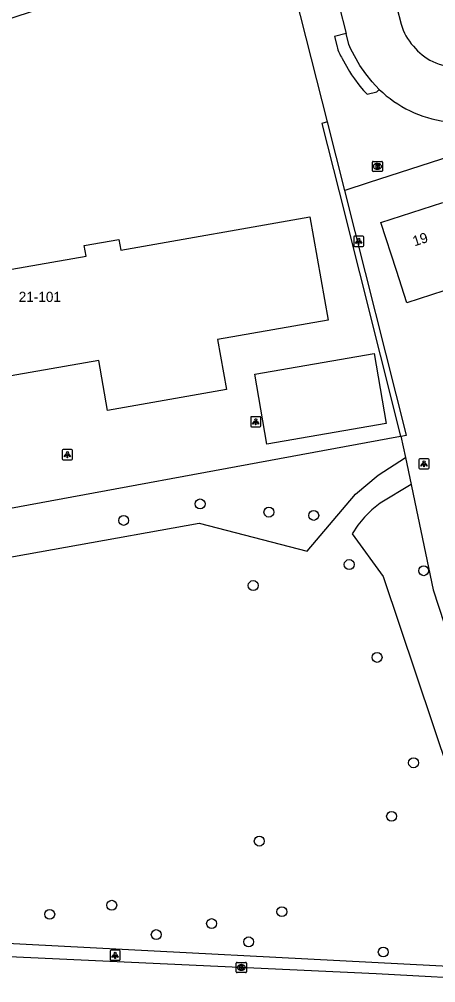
# Model space of a CAD drawing. Extents: x 161253 to 161848, y 384872 to 385383.
# Drawn here: x 161391.4 to 161432.4, y 384951.8 to 385046.9 of the extents above; entities that cross this region are included whole.
import ezdxf

# ---------------------------------------------------------------- set-up
doc = ezdxf.new("R2010")
doc.units = 0
for name, color, linetype in [('IMGEO_Boom', 7, 'Continuous'), ('IMGEO_Brandkraan', 7, 'Continuous'), ('IMGEO_Groenvoorziening', 7, 'Continuous'), ('IMGEO_Haag', 7, 'Continuous'), ('IMGEO_Kolk', 7, 'Continuous'), ('IMGEO_Lichtpunt', 7, 'Continuous'), ('IMGEO_Pand', 7, 'Continuous'), ('IMGEO_Pand_nummerreeks', 7, 'Continuous'), ('IMGEO_Pand_vergunning_verleend', 7, 'Continuous'), ('IMGEO_Rijbaan_lokaal_open', 7, 'Continuous'), ('IMGEO_Voetpad_open', 7, 'Continuous')]:
    doc.layers.add(name, color=color, linetype=linetype)

msp = doc.modelspace()

# ---------------------------------------------------------------- linework, layer by layer
at = {"layer": 'IMGEO_Boom'}
for centre in [(161409.193, 384999.044), (161415.979, 384998.236), (161401.652, 384997.416), (161420.399, 384997.91), (161423.899, 384993.064), (161431.249, 384992.453), (161414.431, 384990.989), (161426.651, 384983.899), (161430.243, 384973.495), (161428.081, 384968.214), (161415.029, 384965.761), (161400.476, 384959.436), (161394.357, 384958.539), (161417.258, 384958.8), (161410.326, 384957.625), (161404.866, 384956.537), (161413.98, 384955.819), (161427.258, 384954.817)]:
    msp.add_circle(centre, 0.489, dxfattribs=at)
at = {"layer": 'IMGEO_Brandkraan'}
for p, q in [((161426.183, 385031.932), (161426.183, 385032.784)), ((161426.258, 385032.858), (161427.11, 385032.858)), ((161426.694, 385032.078), (161426.669, 385032.078)), ((161426.671, 385032.638), (161426.696, 385032.638)), ((161427.184, 385032.784), (161427.184, 385031.932)), ((161427.11, 385031.858), (161426.258, 385031.858))]:
    msp.add_line(p, q, dxfattribs=at)
for points in [[(161426.183, 385031.932), (161426.183, 385032.784)], [(161426.258, 385032.858), (161427.11, 385032.858)], [(161426.531, 385032.558), (161426.531, 385032.158), (161426.744, 385032.158)], [(161426.762, 385032.558), (161426.531, 385032.558)], [(161426.71, 385032.477), (161426.656, 385032.477), (161426.656, 385032.401)], [(161426.656, 385032.401), (161426.709, 385032.401)], [(161426.718, 385032.325), (161426.656, 385032.325), (161426.656, 385032.244)], [(161426.656, 385032.244), (161426.718, 385032.244)], [(161427.184, 385032.784), (161427.184, 385031.932)], [(161427.11, 385031.858), (161426.258, 385031.858)]]:
    msp.add_lwpolyline(points, dxfattribs=at)
for centre, radius, start, end in [((161426.26, 385032.782), 0.0765, 91.55205, 178.44795), ((161426.26, 385032.782), 0.0765, 91.55205, 178.44795), ((161426.711, 385032.439), 0.0379, 267.82845, 90.93552), ((161426.719, 385032.284), 0.0404, 269.87594, 90.50774), ((161426.75, 385032.409), 0.251, 268.66757, 293.53466), ((161426.766, 385032.413), 0.145, 59.4692, 91.53667), ((161426.791, 385032.46), 0.0922, 285.51372, 58.15012), ((161426.796, 385032.268), 0.105, 301.31148, 78.98903), ((161427.108, 385032.782), 0.0765, 1.55205, 88.44795), ((161427.108, 385032.782), 0.0765, 1.55205, 88.44795), ((161426.26, 385031.934), 0.0765, 181.55205, 268.44795), ((161426.26, 385031.934), 0.0765, 181.55205, 268.44795), ((161427.108, 385031.934), 0.0765, 271.55205, 358.44795), ((161427.108, 385031.934), 0.0765, 271.55205, 358.44795)]:
    msp.add_arc(centre, radius, start, end, dxfattribs=at)
for centre, major_axis, ratio, start_param, end_param in [((161426.67, 385032.358), (-0.387, 0.002), 0.722429, 4.712389, 7.853982), ((161426.695, 385032.358), (-0.39, 0.002), 0.717154, 1.570796, 4.712389)]:
    msp.add_ellipse(centre, major_axis=major_axis, ratio=ratio, start_param=start_param, end_param=end_param, dxfattribs=at)
at = {"layer": 'IMGEO_Groenvoorziening'}
for points in [[(161381.538, 384996.968), (161428.963, 385005.723)], [(161429.001, 385005.73), (161429.448, 385003.612)], [(161385.699, 384955.916), (161382.254, 384992.314), (161382.704, 384992.395), (161409.099, 384997.144), (161419.747, 384994.367), (161424.534, 385000), (161426.767, 385001.869), (161429.448, 385003.612)], [(161429.448, 385003.612), (161430.009, 385000.952)], [(161430.009, 385000.952), (161426.954, 384999.107), (161426.145, 384998.467), (161425.408, 384997.745), (161424.75, 384996.95), (161424.179, 384996.091), (161427.248, 384991.885), (161440.288, 384952.96)], [(161430.009, 385000.952), (161430.209, 385000), (161432.194, 384990.572), (161444.094, 384954.097), (161443.567, 384951.787)]]:
    msp.add_lwpolyline(points, dxfattribs=at)
at = {"layer": 'IMGEO_Haag'}
for points in [[(161421.765, 385036.754), (161421.184, 385036.607), (161422.894, 385029.848), (161428.963, 385005.723)], [(161429.001, 385005.73), (161429.554, 385005.833), (161423.476, 385029.994)], [(161428.963, 385005.723), (161429.001, 385005.73)]]:
    msp.add_lwpolyline(points, dxfattribs=at)
at = {"layer": 'IMGEO_Kolk'}
for p, q in [((161412.759, 384952.865), (161412.759, 384953.717)), ((161412.834, 384953.791), (161413.686, 384953.791)), ((161413.247, 384953.571), (161413.272, 384953.571)), ((161413.76, 384953.717), (161413.76, 384952.865)), ((161413.686, 384952.791), (161412.834, 384952.791)), ((161413.27, 384953.011), (161413.245, 384953.011))]:
    msp.add_line(p, q, dxfattribs=at)
for points in [[(161412.759, 384952.865), (161412.759, 384953.717)], [(161412.834, 384953.791), (161413.686, 384953.791)], [(161413.08, 384953.491), (161413.203, 384953.491), (161413.203, 384953.34), (161413.333, 384953.491), (161413.497, 384953.491), (161413.351, 384953.34), (161413.504, 384953.091), (161413.352, 384953.091), (161413.267, 384953.255), (161413.203, 384953.188), (161413.203, 384953.091), (161413.08, 384953.091), (161413.08, 384953.491)], [(161413.76, 384953.717), (161413.76, 384952.865)], [(161413.686, 384952.791), (161412.834, 384952.791)]]:
    msp.add_lwpolyline(points, dxfattribs=at)
for centre, start, end in [((161412.836, 384953.715), 91.55205, 178.44795), ((161412.836, 384953.715), 91.55205, 178.44795), ((161413.684, 384953.715), 1.55205, 88.44795), ((161413.684, 384953.715), 1.55205, 88.44795), ((161412.836, 384952.867), 181.55205, 268.44795), ((161412.836, 384952.867), 181.55205, 268.44795), ((161413.684, 384952.867), 271.55205, 358.44795), ((161413.684, 384952.867), 271.55205, 358.44795)]:
    msp.add_arc(centre, 0.0765, start, end, dxfattribs=at)
for centre, major_axis, ratio, start_param, end_param in [((161413.246, 384953.291), (-0.387, 0.002), 0.722429, 4.712389, 7.853982), ((161413.271, 384953.291), (-0.39, 0.002), 0.717154, 1.570796, 4.712389)]:
    msp.add_ellipse(centre, major_axis=major_axis, ratio=ratio, start_param=start_param, end_param=end_param, dxfattribs=at)
at = {"layer": 'IMGEO_Lichtpunt'}
for p, q in [((161424.342, 385025.37), (161424.342, 385024.563)), ((161424.342, 385025.37), (161424.342, 385024.563)), ((161425.244, 385025.465), (161424.436, 385025.465)), ((161425.244, 385025.465), (161424.436, 385025.465)), ((161425.338, 385024.563), (161425.338, 385025.37)), ((161425.338, 385024.563), (161425.338, 385025.37)), ((161424.436, 385024.469), (161425.244, 385024.469)), ((161424.436, 385024.469), (161425.244, 385024.469)), ((161414.182, 385007.559), (161414.182, 385006.752)), ((161414.182, 385007.559), (161414.182, 385006.752)), ((161415.084, 385007.654), (161414.276, 385007.654)), ((161415.084, 385007.654), (161414.276, 385007.654)), ((161415.178, 385006.752), (161415.178, 385007.559)), ((161415.178, 385006.752), (161415.178, 385007.559)), ((161414.276, 385006.658), (161415.084, 385006.658)), ((161414.276, 385006.658), (161415.084, 385006.658)), ((161396.504, 385004.406), (161395.696, 385004.406)), ((161396.504, 385004.406), (161395.696, 385004.406)), ((161395.602, 385004.311), (161395.602, 385003.504)), ((161395.602, 385004.311), (161395.602, 385003.504)), ((161396.598, 385003.504), (161396.598, 385004.311)), ((161396.598, 385003.504), (161396.598, 385004.311)), ((161431.682, 385003.496), (161430.874, 385003.496)), ((161431.682, 385003.496), (161430.874, 385003.496)), ((161395.696, 385003.41), (161396.504, 385003.41)), ((161395.696, 385003.41), (161396.504, 385003.41)), ((161430.78, 385003.401), (161430.78, 385002.594)), ((161430.78, 385003.401), (161430.78, 385002.594)), ((161431.776, 385002.594), (161431.776, 385003.401)), ((161431.776, 385002.594), (161431.776, 385003.401)), ((161430.874, 385002.5), (161431.682, 385002.5)), ((161430.874, 385002.5), (161431.682, 385002.5)), ((161401.213, 384954.994), (161400.405, 384954.994)), ((161401.213, 384954.994), (161400.405, 384954.994)), ((161400.311, 384954.899), (161400.311, 384954.092)), ((161400.311, 384954.899), (161400.311, 384954.092)), ((161401.307, 384954.092), (161401.307, 384954.899)), ((161401.307, 384954.092), (161401.307, 384954.899)), ((161400.405, 384953.998), (161401.213, 384953.998)), ((161400.405, 384953.998), (161401.213, 384953.998))]:
    msp.add_line(p, q, dxfattribs=at)
for points in [[(161424.716, 385025.034), (161424.755, 385025.006), (161424.567, 385024.744), (161424.529, 385024.771), (161424.716, 385025.034)], [(161424.818, 385024.986), (161424.865, 385024.986), (161424.865, 385024.664), (161424.818, 385024.664), (161424.818, 385024.986)], [(161424.928, 385025.006), (161424.966, 385025.033), (161425.153, 385024.771), (161425.114, 385024.743), (161424.928, 385025.006)], [(161414.556, 385007.223), (161414.595, 385007.195), (161414.407, 385006.933), (161414.369, 385006.96), (161414.556, 385007.223)], [(161414.658, 385007.175), (161414.705, 385007.175), (161414.705, 385006.853), (161414.658, 385006.853), (161414.658, 385007.175)], [(161414.768, 385007.195), (161414.806, 385007.222), (161414.993, 385006.96), (161414.954, 385006.932), (161414.768, 385007.195)], [(161395.976, 385003.975), (161396.015, 385003.947), (161395.827, 385003.685), (161395.789, 385003.712), (161395.976, 385003.975)], [(161396.078, 385003.927), (161396.125, 385003.927), (161396.125, 385003.605), (161396.078, 385003.605), (161396.078, 385003.927)], [(161396.188, 385003.947), (161396.226, 385003.974), (161396.413, 385003.712), (161396.374, 385003.684), (161396.188, 385003.947)], [(161431.154, 385003.065), (161431.193, 385003.037), (161431.005, 385002.775), (161430.967, 385002.802), (161431.154, 385003.065)], [(161431.256, 385003.017), (161431.303, 385003.017), (161431.303, 385002.695), (161431.256, 385002.695), (161431.256, 385003.017)], [(161431.366, 385003.037), (161431.404, 385003.064), (161431.591, 385002.802), (161431.552, 385002.774), (161431.366, 385003.037)], [(161400.685, 384954.563), (161400.724, 384954.535), (161400.536, 384954.273), (161400.498, 384954.3), (161400.685, 384954.563)], [(161400.787, 384954.515), (161400.834, 384954.515), (161400.834, 384954.193), (161400.787, 384954.193), (161400.787, 384954.515)], [(161400.897, 384954.535), (161400.935, 384954.562), (161401.122, 384954.3), (161401.083, 384954.272), (161400.897, 384954.535)]]:
    msp.add_lwpolyline(points, dxfattribs=at)
for centre in [(161424.841, 385025.168), (161414.681, 385007.357), (161396.101, 385004.109), (161431.279, 385003.199), (161400.81, 384954.697)]:
    msp.add_circle(centre, 0.0994, dxfattribs=at)
for centre, start, end in [((161424.436, 385025.37), 90, 180), ((161424.436, 385025.37), 90, 180), ((161425.244, 385025.37), 0, 90), ((161425.244, 385025.37), 0, 90), ((161424.436, 385024.563), 180, 270), ((161424.436, 385024.563), 180, 270), ((161425.244, 385024.563), 270, 0), ((161425.244, 385024.563), 270, 360), ((161414.276, 385007.559), 90, 180), ((161414.276, 385007.559), 90, 180), ((161415.084, 385007.559), 0, 90), ((161415.084, 385007.559), 0, 90), ((161414.276, 385006.752), 180, 270), ((161414.276, 385006.752), 180, 270), ((161415.084, 385006.752), 270, 0), ((161415.084, 385006.752), 270, 360), ((161395.696, 385004.311), 90, 180), ((161395.696, 385004.311), 90, 180), ((161396.504, 385004.311), 0, 90), ((161396.504, 385004.311), 0, 90), ((161395.696, 385003.504), 180, 270), ((161395.696, 385003.504), 180, 270), ((161396.504, 385003.504), 270, 0), ((161396.504, 385003.504), 270, 360), ((161430.874, 385003.401), 90, 180), ((161430.874, 385003.401), 90, 180), ((161431.682, 385003.401), 0, 90), ((161431.682, 385003.401), 0, 90), ((161430.874, 385002.594), 180, 270), ((161430.874, 385002.594), 180, 270), ((161431.682, 385002.594), 270, 0), ((161431.682, 385002.594), 270, 360), ((161400.405, 384954.899), 90, 180), ((161400.405, 384954.899), 90, 180), ((161401.213, 384954.899), 0, 90), ((161401.213, 384954.899), 0, 90), ((161400.405, 384954.092), 180, 270), ((161400.405, 384954.092), 180, 270), ((161401.213, 384954.092), 270, 0), ((161401.213, 384954.092), 270, 360)]:
    msp.add_arc(centre, 0.0946, start, end, dxfattribs=at)
at = {"layer": 'IMGEO_Pand'}
for points in [[(161435.659, 385020.873), (161429.587, 385018.907), (161428.56, 385022.078), (161427.02, 385026.834), (161433.121, 385028.81)], [(161420.032, 385027.376), (161421.824, 385017.197), (161410.922, 385015.279), (161411.792, 385010.335), (161400.072, 385008.273), (161399.202, 385013.217), (161380.907, 385009.997), (161379.113, 385020.193), (161397.947, 385023.507), (161397.765, 385024.537), (161401.183, 385025.139), (161401.368, 385024.092), (161420.032, 385027.376)]]:
    msp.add_lwpolyline(points, dxfattribs=at)
at = {"layer": 'IMGEO_Pand_vergunning_verleend'}
msp.add_lwpolyline([(161414.582, 385011.86), (161426.351, 385013.889), (161427.545, 385006.967), (161415.776, 385004.937), (161414.582, 385011.86)], dxfattribs=at)
at = {"layer": 'IMGEO_Rijbaan_lokaal_open'}
for points in [[(161426.814, 385054.752), (161427.573, 385051.945), (161428.592, 385048.045), (161429.019, 385046.404)], [(161421.537, 385053.595), (161423.592, 385045.476)], [(161426.863, 385039.954), (161426.15, 385040.699), (161425.524, 385041.489), (161424.959, 385042.314), (161424.058, 385043.921), (161423.869, 385044.38), (161423.592, 385045.476)], [(161438.622, 384952.015), (161426.573, 384952.665), (161402.419, 384953.798), (161366.213, 384955.463), (161364.762, 384955.736), (161364.406, 384955.834), (161363.914, 384956.01), (161363.438, 384956.23), (161362.985, 384956.491), (161362.556, 384956.792), (161362.157, 384957.13), (161361.789, 384957.502), (161361.455, 384957.906), (161361.159, 384958.338), (161360.903, 384958.794), (161360.689, 384959.272), (161360.518, 384959.767), (161360.392, 384960.275), (161360.312, 384960.792), (161359.166, 384970.229)]]:
    msp.add_lwpolyline(points, dxfattribs=at)
for centre, radius, start, end in [((161433.968, 385047.747), 5.128, 195.18046, 223.29954), ((161434.53, 385047.676), 5.506, 218.74948, 244.20384), ((161435.55, 385050.085), 8.119, 245.11673, 265.09381), ((161435.052, 385048.503), 11.838, 226.23335, 262.1461)]:
    msp.add_arc(centre, radius, start, end, dxfattribs=at)
at = {"layer": 'IMGEO_Voetpad_open'}
for points in [[(161421.765, 385036.754), (161417, 385055.584), (161373.417, 385041.421)], [(161488.637, 385051.077), (161425.757, 385030.732), (161423.476, 385029.994)], [(161423.592, 385045.476), (161422.451, 385045.179), (161422.698, 385044.173)], [(161423.208, 385043.003), (161423.928, 385041.72), (161424.14, 385041.383), (161424.408, 385041.015), (161424.85, 385040.405), (161425.111, 385040.08), (161425.317, 385039.862), (161425.683, 385039.474), (161426.618, 385039.719), (161426.863, 385039.954)], [(161423.476, 385029.994), (161421.765, 385036.754)], [(161385.699, 384955.916), (161438.755, 384953.144), (161440.288, 384952.96)]]:
    msp.add_lwpolyline(points, dxfattribs=at)
msp.add_arc((161426.675, 385045.21), 4.11, 194.62038, 212.48414, dxfattribs=at)

# ---------------------------------------------------------------- texts
at = {"layer": 'IMGEO_Pand_nummerreeks'}
for s, rotation, p in [('19', 17.94557, (161430.348, 385024.463)), ('21-101', 360, (161391.301, 385018.982))]:
    msp.add_text(s, height=1, rotation=rotation, dxfattribs=at).set_placement(p)

doc.saveas('drawing.dxf')
